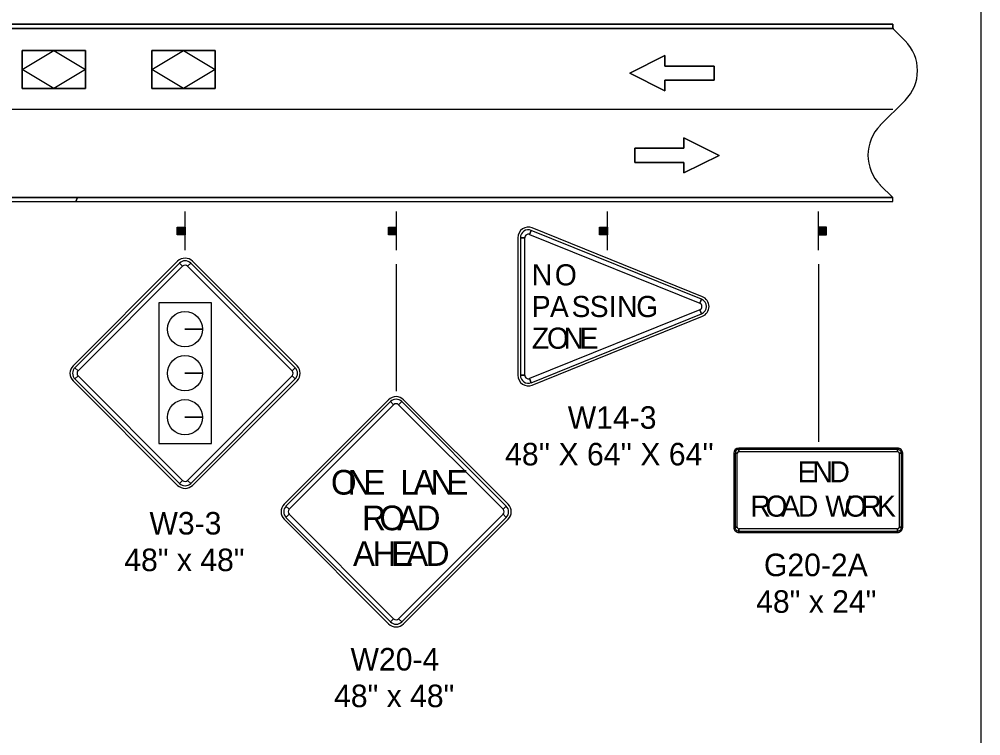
# Model space of a CAD drawing. Extents: x -2134934 to -2127057, y -2139046 to -2137036.
# Drawn here: x -2132482 to -2131799, y -2138047 to -2137539 of the extents above; entities that cross this region are included whole.
import ezdxf

# ---------------------------------------------------------------- set-up
doc = ezdxf.new("R2010")
doc.units = 0
for name, color, linetype in [('Barrier', 7, 'Continuous'), ('BridgeSuperStructureExisting', 7, 'Continuous'), ('Default', 7, 'Continuous'), ('DsnShtPlotIdentification', 7, 'Continuous'), ('dsnTextFinalPlan', 7, 'Continuous')]:
    doc.layers.add(name, color=color, linetype=linetype)

msp = doc.modelspace()

# ---------------------------------------------------------------- linework, layer by layer
at = {"layer": 'Barrier'}
for p, q in [((-2132119.84, -2137691.45), (-2132118.67, -2137688.56)), ((-2131997.15, -2137735.69), (-2132117.97, -2137686.82)), ((-2132128.28, -2137693.77), (-2132128.28, -2137791.52)), ((-2132126.41, -2137693.77), (-2132123.28, -2137693.77)), ((-2132369.87, -2137710.55), (-2132444.11, -2137784.8)), ((-2132368.54, -2137711.88), (-2132366.33, -2137714.08)), ((-2132362.8, -2137714.08), (-2132360.59, -2137711.88)), ((-2132285.02, -2137784.8), (-2132359.26, -2137710.55)), ((-2131997.85, -2137737.43), (-2131999.02, -2137740.33)), ((-2132117.97, -2137798.48), (-2131997.15, -2137749.6)), ((-2131999.02, -2137744.96), (-2131997.85, -2137747.86)), ((-2132352.16, -2137758.77), (-2132364.66, -2137758.77)), ((-2132364.66, -2137758.77), (-2132352.16, -2137758.77)), ((-2132440.58, -2137788.33), (-2132442.79, -2137786.12)), ((-2132442.79, -2137794.08), (-2132440.58, -2137791.87)), ((-2132352.16, -2137790.02), (-2132364.66, -2137790.02)), ((-2132364.66, -2137790.02), (-2132352.16, -2137790.02)), ((-2132286.34, -2137786.12), (-2132288.55, -2137788.33)), ((-2132288.55, -2137791.87), (-2132286.34, -2137794.08)), ((-2132123.28, -2137791.52), (-2132126.41, -2137791.52)), ((-2132444.11, -2137795.4), (-2132369.87, -2137869.65)), ((-2132359.26, -2137869.65), (-2132285.02, -2137795.4)), ((-2132118.67, -2137796.74), (-2132119.84, -2137793.84)), ((-2132219.98, -2137808.84), (-2132294.23, -2137883.09)), ((-2132218.66, -2137810.17), (-2132216.45, -2137812.38)), ((-2132212.91, -2137812.38), (-2132210.7, -2137810.17)), ((-2132135.13, -2137883.09), (-2132209.38, -2137808.84)), ((-2132352.16, -2137821.27), (-2132364.66, -2137821.27)), ((-2132364.66, -2137821.27), (-2132352.16, -2137821.27)), ((-2131974.91, -2137846.89), (-2131974.91, -2137899.39)), ((-2131973.97, -2137846.89), (-2131972.41, -2137846.89)), ((-2131858.66, -2137843.14), (-2131971.16, -2137843.14)), ((-2131971.16, -2137845.64), (-2131971.16, -2137844.08)), ((-2131858.66, -2137844.08), (-2131858.66, -2137845.64)), ((-2131857.41, -2137846.89), (-2131855.85, -2137846.89)), ((-2131854.91, -2137899.39), (-2131854.91, -2137846.89)), ((-2132366.33, -2137866.11), (-2132368.54, -2137868.32)), ((-2132360.59, -2137868.32), (-2132362.8, -2137866.11)), ((-2132290.69, -2137886.62), (-2132292.9, -2137884.41)), ((-2132136.46, -2137884.41), (-2132138.66, -2137886.62)), ((-2132294.23, -2137893.69), (-2132219.98, -2137967.94)), ((-2132292.9, -2137892.37), (-2132290.69, -2137890.16)), ((-2132209.38, -2137967.94), (-2132135.13, -2137893.69)), ((-2132138.66, -2137890.16), (-2132136.46, -2137892.37)), ((-2131972.41, -2137899.39), (-2131973.97, -2137899.39)), ((-2131971.16, -2137902.2), (-2131971.16, -2137900.64)), ((-2131858.66, -2137900.64), (-2131858.66, -2137902.2)), ((-2131855.85, -2137899.39), (-2131857.41, -2137899.39)), ((-2131971.16, -2137903.14), (-2131858.66, -2137903.14)), ((-2132216.45, -2137964.41), (-2132218.66, -2137966.61)), ((-2132210.7, -2137966.61), (-2132212.91, -2137964.41))]:
    msp.add_line(p, q, dxfattribs=at)
for points in [[(-2131997.85, -2137737.43), (-2132118.67, -2137688.56), (-2132119.84, -2137691.45), (-2131999.02, -2137740.33), (-2131997.85, -2137737.43)], [(-2132126.41, -2137693.77), (-2132126.41, -2137791.52), (-2132123.28, -2137791.52), (-2132123.28, -2137693.77), (-2132126.41, -2137693.77)], [(-2132368.54, -2137711.88), (-2132442.79, -2137786.12), (-2132440.58, -2137788.33), (-2132366.33, -2137714.08), (-2132368.54, -2137711.88)], [(-2132286.34, -2137786.12), (-2132360.59, -2137711.88), (-2132362.8, -2137714.08), (-2132288.55, -2137788.33), (-2132286.34, -2137786.12)], [(-2132345.83, -2137740.15), (-2132383.3, -2137740.15), (-2132383.3, -2137840.04), (-2132345.83, -2137840.04), (-2132345.83, -2137740.15)], [(-2132118.67, -2137796.74), (-2131997.85, -2137747.86), (-2131999.02, -2137744.96), (-2132119.84, -2137793.84), (-2132118.67, -2137796.74)], [(-2132442.79, -2137794.08), (-2132368.54, -2137868.32), (-2132366.33, -2137866.11), (-2132440.58, -2137791.87), (-2132442.79, -2137794.08)], [(-2132360.59, -2137868.32), (-2132286.34, -2137794.08), (-2132288.55, -2137791.87), (-2132362.8, -2137866.11), (-2132360.59, -2137868.32)], [(-2132218.66, -2137810.17), (-2132292.9, -2137884.41), (-2132290.69, -2137886.62), (-2132216.45, -2137812.38), (-2132218.66, -2137810.17)], [(-2132136.46, -2137884.41), (-2132210.7, -2137810.17), (-2132212.91, -2137812.38), (-2132138.66, -2137886.62), (-2132136.46, -2137884.41)], [(-2131973.97, -2137846.89), (-2131973.97, -2137899.39), (-2131972.41, -2137899.39), (-2131972.41, -2137846.89), (-2131973.97, -2137846.89)], [(-2131858.66, -2137844.08), (-2131971.16, -2137844.08), (-2131971.16, -2137845.64), (-2131858.66, -2137845.64), (-2131858.66, -2137844.08)], [(-2131855.85, -2137899.39), (-2131855.85, -2137846.89), (-2131857.41, -2137846.89), (-2131857.41, -2137899.39), (-2131855.85, -2137899.39)], [(-2132292.9, -2137892.37), (-2132218.66, -2137966.61), (-2132216.45, -2137964.41), (-2132290.69, -2137890.16), (-2132292.9, -2137892.37)], [(-2132210.7, -2137966.61), (-2132136.46, -2137892.37), (-2132138.66, -2137890.16), (-2132212.91, -2137964.41), (-2132210.7, -2137966.61)], [(-2131971.16, -2137902.2), (-2131858.66, -2137902.2), (-2131858.66, -2137900.64), (-2131971.16, -2137900.64), (-2131971.16, -2137902.2)]]:
    msp.add_lwpolyline(points, close=True, dxfattribs=at)
for centre in [(-2132364.66, -2137758.77), (-2132364.66, -2137790.02), (-2132364.66, -2137821.27)]:
    msp.add_circle(centre, 12.5, dxfattribs=at)
for centre, radius, start, end in [((-2132120.78, -2137693.77), 7.5, 67.97571, 179.99985), ((-2132120.78, -2137693.77), 5.62, 67.97571, 179.99985), ((-2132120.78, -2137693.77), 2.5, 67.97571, 179.99985), ((-2132364.57, -2137715.85), 7.5, 44.99999, 134.99974), ((-2132364.57, -2137715.85), 5.62, 44.99999, 134.99974), ((-2132364.57, -2137715.85), 2.5, 44.99999, 134.99974), ((-2131999.96, -2137742.65), 5.62, 292.02456, 67.97541), ((-2131999.96, -2137742.65), 7.5, 292.02456, 67.97598), ((-2131999.96, -2137742.65), 2.5, 292.02456, 67.97541), ((-2132438.81, -2137790.1), 7.5, 134.99974, 224.99995), ((-2132290.32, -2137790.1), 7.5, 315.00016, 44.9998), ((-2132438.81, -2137790.1), 5.62, 134.99974, 224.99995), ((-2132438.81, -2137790.1), 2.5, 134.99974, 224.99995), ((-2132290.32, -2137790.1), 2.5, 315.00016, 44.9998), ((-2132290.32, -2137790.1), 5.62, 315.00016, 44.9998), ((-2132120.78, -2137791.52), 7.5, 179.99985, 292.02456), ((-2132120.78, -2137791.52), 5.62, 179.99985, 292.02456), ((-2132120.78, -2137791.52), 2.5, 179.99985, 292.02456), ((-2132214.68, -2137814.15), 7.5, 44.99999, 134.99974), ((-2132214.68, -2137814.15), 5.62, 44.99999, 134.99974), ((-2132214.68, -2137814.15), 2.5, 44.99999, 134.99974), ((-2131971.16, -2137846.89), 3.75, 90.00021, 179.99985), ((-2131971.16, -2137846.89), 2.81, 90.00021, 179.99985), ((-2131971.16, -2137846.89), 1.25, 90.00021, 179.99985), ((-2131858.66, -2137846.89), 3.75, 0, 90.00021), ((-2131858.66, -2137846.89), 2.81, 0, 90.00021), ((-2131858.66, -2137846.89), 1.25, 0, 90.00021), ((-2132364.57, -2137864.34), 2.5, 224.99995, 315.00016), ((-2132364.57, -2137864.34), 7.5, 224.99995, 315.00016), ((-2132364.57, -2137864.34), 5.62, 224.99995, 315.00016), ((-2132288.92, -2137888.39), 7.5, 134.99974, 224.99995), ((-2132288.92, -2137888.39), 5.62, 134.99974, 224.99995), ((-2132288.92, -2137888.39), 2.5, 134.99974, 224.99995), ((-2132140.43, -2137888.39), 2.5, 315.00016, 44.9998), ((-2132140.43, -2137888.39), 5.62, 315.00016, 44.9998), ((-2132140.43, -2137888.39), 7.5, 315.00016, 44.9998), ((-2131971.16, -2137899.39), 3.75, 179.99985, 270.00006), ((-2131971.16, -2137899.39), 2.81, 179.99985, 270.00006), ((-2131971.16, -2137899.39), 1.25, 179.99985, 270.00006), ((-2131858.66, -2137899.39), 3.75, 270.00006, 0.00027), ((-2131858.66, -2137899.39), 2.81, 270.00006, 0.00027), ((-2131858.66, -2137899.39), 1.25, 270.00006, 0.00027), ((-2132214.68, -2137962.64), 7.5, 224.99995, 315.00016), ((-2132214.68, -2137962.64), 5.62, 224.99995, 315.00016), ((-2132214.68, -2137962.64), 2.5, 224.99995, 315.00016)]:
    msp.add_arc(centre, radius, start, end, dxfattribs=at)
at = {"layer": 'BridgeSuperStructureExisting'}
for p, q in [((-2131861.99, -2137545.16), (-2133174.44, -2137545.16)), ((-2131853.21, -2137553.94), (-2131861.99, -2137545.16)), ((-2131853.2, -2137553.95), (-2131861.99, -2137545.16)), ((-2132480.28, -2137587.78), (-2132480.28, -2137560.78)), ((-2132480.28, -2137560.78), (-2132435.28, -2137560.78)), ((-2132480.28, -2137587.78), (-2132480.28, -2137560.78)), ((-2132480.28, -2137560.78), (-2132435.28, -2137560.78)), ((-2132435.28, -2137560.78), (-2132480.28, -2137560.78)), ((-2132480.28, -2137560.78), (-2132480.28, -2137587.78)), ((-2132435.28, -2137587.78), (-2132435.28, -2137560.78)), ((-2132435.28, -2137560.78), (-2132435.28, -2137587.78)), ((-2132435.28, -2137587.78), (-2132435.28, -2137560.78)), ((-2132388.09, -2137587.86), (-2132388.09, -2137560.86)), ((-2132388.09, -2137560.86), (-2132343.09, -2137560.86)), ((-2132388.09, -2137587.86), (-2132388.09, -2137560.86)), ((-2132388.09, -2137560.86), (-2132343.09, -2137560.86)), ((-2132343.09, -2137560.86), (-2132388.09, -2137560.86)), ((-2132388.09, -2137560.86), (-2132388.09, -2137587.86)), ((-2132343.09, -2137587.86), (-2132343.09, -2137560.86)), ((-2132343.09, -2137560.86), (-2132343.09, -2137587.86)), ((-2132343.09, -2137587.86), (-2132343.09, -2137560.86)), ((-2132480.28, -2137587.78), (-2132435.28, -2137587.78)), ((-2132435.28, -2137587.78), (-2132480.28, -2137587.78)), ((-2132480.28, -2137587.78), (-2132435.28, -2137587.78)), ((-2132388.09, -2137587.86), (-2132343.09, -2137587.86)), ((-2132343.09, -2137587.86), (-2132388.09, -2137587.86)), ((-2132388.09, -2137587.86), (-2132343.09, -2137587.86)), ((-2131870.78, -2137613.94), (-2131853.21, -2137596.37)), ((-2131870.78, -2137613.95), (-2131853.2, -2137596.37)), ((-2131861.99, -2137665.16), (-2131870.78, -2137656.37)), ((-2131861.99, -2137665.16), (-2131870.78, -2137656.37)), ((-2133364.44, -2137665.16), (-2131861.99, -2137665.16)), ((-2132364.45, -2137702.66), (-2132364.45, -2137675.16)), ((-2132214.45, -2137702.66), (-2132214.45, -2137675.16)), ((-2132064.45, -2137702.66), (-2132064.45, -2137675.16)), ((-2131914.64, -2137702.66), (-2131914.64, -2137675.16)), ((-2132369.77, -2137691.8), (-2132369.77, -2137686.21)), ((-2132369.45, -2137686.21), (-2132369.45, -2137691.8)), ((-2132369.23, -2137691.8), (-2132369.23, -2137686.21)), ((-2132368.91, -2137686.21), (-2132368.91, -2137691.8)), ((-2132368.68, -2137691.8), (-2132368.7, -2137686.21)), ((-2132368.27, -2137686.21), (-2132368.25, -2137691.8)), ((-2132368.05, -2137691.8), (-2132368.05, -2137686.21)), ((-2132367.62, -2137686.21), (-2132367.62, -2137691.8)), ((-2132367.24, -2137691.8), (-2132367.24, -2137686.21)), ((-2132366.92, -2137686.21), (-2132366.9, -2137691.8)), ((-2132366.7, -2137691.8), (-2132366.7, -2137686.21)), ((-2132366.43, -2137686.21), (-2132366.43, -2137691.8)), ((-2132366.1, -2137691.8), (-2132366.1, -2137686.21)), ((-2132365.89, -2137686.21), (-2132365.89, -2137691.8)), ((-2132365.67, -2137691.8), (-2132365.67, -2137686.21)), ((-2132365.4, -2137686.21), (-2132365.4, -2137691.8)), ((-2132365.14, -2137691.8), (-2132365.14, -2137686.21)), ((-2132364.86, -2137686.21), (-2132364.86, -2137691.8)), ((-2132219.77, -2137691.8), (-2132219.77, -2137686.21)), ((-2132219.45, -2137686.21), (-2132219.45, -2137691.8)), ((-2132219.23, -2137691.8), (-2132219.23, -2137686.21)), ((-2132218.91, -2137686.21), (-2132218.91, -2137691.8)), ((-2132218.69, -2137691.8), (-2132218.7, -2137686.21)), ((-2132218.27, -2137686.21), (-2132218.25, -2137691.8)), ((-2132218.05, -2137691.8), (-2132218.05, -2137686.21)), ((-2132217.62, -2137686.21), (-2132217.62, -2137691.8)), ((-2132217.24, -2137691.8), (-2132217.24, -2137686.21)), ((-2132216.92, -2137686.21), (-2132216.9, -2137691.8)), ((-2132216.7, -2137691.8), (-2132216.7, -2137686.21)), ((-2132216.43, -2137686.21), (-2132216.43, -2137691.8)), ((-2132216.1, -2137691.8), (-2132216.1, -2137686.21)), ((-2132215.89, -2137686.21), (-2132215.89, -2137691.8)), ((-2132215.67, -2137691.8), (-2132215.67, -2137686.21)), ((-2132215.4, -2137686.21), (-2132215.4, -2137691.8)), ((-2132215.14, -2137691.8), (-2132215.14, -2137686.21)), ((-2132214.86, -2137686.21), (-2132214.86, -2137691.8)), ((-2132069.77, -2137691.8), (-2132069.77, -2137686.21)), ((-2132069.45, -2137686.21), (-2132069.45, -2137691.8)), ((-2132069.23, -2137691.8), (-2132069.23, -2137686.21)), ((-2132068.91, -2137686.21), (-2132068.91, -2137691.8)), ((-2132068.69, -2137691.8), (-2132068.7, -2137686.21)), ((-2132068.27, -2137686.21), (-2132068.25, -2137691.8)), ((-2132068.05, -2137691.8), (-2132068.05, -2137686.21)), ((-2132067.62, -2137686.21), (-2132067.62, -2137691.8)), ((-2132067.24, -2137691.8), (-2132067.24, -2137686.21)), ((-2132066.92, -2137686.21), (-2132066.9, -2137691.8)), ((-2132066.7, -2137691.8), (-2132066.7, -2137686.21)), ((-2132066.43, -2137686.21), (-2132066.43, -2137691.8)), ((-2132066.1, -2137691.8), (-2132066.1, -2137686.21)), ((-2132065.89, -2137686.21), (-2132065.89, -2137691.8)), ((-2132065.67, -2137691.8), (-2132065.67, -2137686.21)), ((-2132065.4, -2137686.21), (-2132065.4, -2137691.8)), ((-2132065.14, -2137691.8), (-2132065.14, -2137686.21)), ((-2132064.86, -2137686.21), (-2132064.86, -2137691.8)), ((-2131914.22, -2137686.21), (-2131914.22, -2137691.8)), ((-2131913.94, -2137691.8), (-2131913.94, -2137686.21)), ((-2131913.68, -2137686.21), (-2131913.68, -2137691.8)), ((-2131913.42, -2137691.8), (-2131913.42, -2137686.21)), ((-2131913.19, -2137686.21), (-2131913.19, -2137691.8)), ((-2131912.99, -2137691.8), (-2131912.99, -2137686.21)), ((-2131912.65, -2137686.21), (-2131912.65, -2137691.8)), ((-2131912.39, -2137691.8), (-2131912.39, -2137686.21)), ((-2131912.16, -2137686.21), (-2131912.18, -2137691.8)), ((-2131911.84, -2137691.8), (-2131911.84, -2137686.21)), ((-2131911.47, -2137686.21), (-2131911.47, -2137691.8)), ((-2131911.04, -2137691.8), (-2131911.04, -2137686.21)), ((-2131910.81, -2137686.21), (-2131910.83, -2137691.8)), ((-2131910.4, -2137691.8), (-2131910.38, -2137686.21)), ((-2131910.17, -2137686.21), (-2131910.17, -2137691.8)), ((-2131909.85, -2137691.8), (-2131909.85, -2137686.21)), ((-2131909.63, -2137686.21), (-2131909.63, -2137691.8)), ((-2131909.31, -2137691.8), (-2131909.31, -2137686.21)), ((-2132214.45, -2137802.66), (-2132214.45, -2137712.66)), ((-2131914.45, -2137838.71), (-2131914.45, -2137712.66))]:
    msp.add_line(p, q, dxfattribs=at)
for points in [[(-2131988.74, -2137582), (-2131988.74, -2137572), (-2132023.74, -2137572), (-2132023.74, -2137564.5), (-2132048.74, -2137577), (-2132023.74, -2137589.5), (-2132023.74, -2137582)], [(-2132045.26, -2137630.33), (-2132045.26, -2137640.33), (-2132010.26, -2137640.33), (-2132010.26, -2137647.83), (-2131985.26, -2137635.33), (-2132010.26, -2137622.83), (-2132010.26, -2137630.33)], [(-2132364.54, -2137686.21), (-2132364.54, -2137691.84), (-2132370.17, -2137691.84), (-2132370.17, -2137686.21)], [(-2132214.54, -2137686.21), (-2132214.54, -2137691.84), (-2132220.17, -2137691.84), (-2132220.17, -2137686.21)], [(-2132064.54, -2137686.21), (-2132064.54, -2137691.84), (-2132070.17, -2137691.84), (-2132070.17, -2137686.21)], [(-2131914.54, -2137686.21), (-2131914.54, -2137691.84), (-2131908.92, -2137691.84), (-2131908.92, -2137686.21)]]:
    msp.add_lwpolyline(points, close=True, dxfattribs=at)
for points in [[(-2132023.74, -2137582), (-2132023.74, -2137589.5), (-2132048.74, -2137577), (-2132023.74, -2137564.5), (-2132023.74, -2137572), (-2131988.74, -2137572), (-2131988.74, -2137582), (-2132023.74, -2137582)], [(-2132010.26, -2137630.33), (-2132010.26, -2137622.83), (-2131985.26, -2137635.33), (-2132010.26, -2137647.83), (-2132010.26, -2137640.33), (-2132045.26, -2137640.33), (-2132045.26, -2137630.33), (-2132010.26, -2137630.33)]]:
    msp.add_lwpolyline(points, dxfattribs=at)
for centre, start, end in [((-2131874.42, -2137575.16), 315, 45), ((-2131874.42, -2137575.16), 315, 45), ((-2131849.56, -2137635.16), 135, 225), ((-2131849.56, -2137635.16), 135, 225)]:
    msp.add_arc(centre, 30, start, end, dxfattribs=at)
at = {"layer": 'Default'}
msp.add_lwpolyline([(-2134934.44, -2137035.95), (-2131799.45, -2137035.95), (-2131799.45, -2139045.94), (-2134934.44, -2139045.94)], close=True, dxfattribs=at)
at = {"layer": 'DsnShtPlotIdentification'}
for p, q in [((-2131861.99, -2137542.16), (-2132547.01, -2137542.16)), ((-2132509.45, -2137545.16), (-2131861.99, -2137545.16)), ((-2131861.99, -2137542.16), (-2131861.99, -2137545.16)), ((-2131861.99, -2137545.16), (-2131861.99, -2137542.16)), ((-2131861.95, -2137602.66), (-2132514.45, -2137602.66)), ((-2133364.44, -2137665.16), (-2131861.99, -2137665.16)), ((-2133364.44, -2137665.16), (-2131861.99, -2137665.16)), ((-2133364.44, -2137668.16), (-2131861.99, -2137668.16)), ((-2132441.05, -2137665.16), (-2132714.94, -2137665.16)), ((-2132714.94, -2137668.16), (-2132442.06, -2137668.16)), ((-2132442.06, -2137668.16), (-2132441.05, -2137665.16)), ((-2132441.05, -2137665.16), (-2132442.06, -2137668.16)), ((-2132442.06, -2137668.16), (-2131861.99, -2137668.16)), ((-2131861.99, -2137665.16), (-2132441.05, -2137665.16)), ((-2131861.99, -2137668.16), (-2131861.99, -2137665.16)), ((-2131861.99, -2137668.16), (-2131861.99, -2137665.16))]:
    msp.add_line(p, q, dxfattribs=at)
for points in [[(-2133174.44, -2137542.16), (-2131861.99, -2137542.16)], [(-2133174.44, -2137545.16), (-2131861.99, -2137545.16)], [(-2133173.75, -2137545.16), (-2131861.29, -2137545.16)]]:
    msp.add_lwpolyline(points, dxfattribs=at)
at = {"layer": 'dsnTextFinalPlan'}
for points in [[(-2132480.28, -2137574.28), (-2132457.78, -2137560.78), (-2132435.28, -2137574.28), (-2132457.78, -2137587.78)], [(-2132388.09, -2137574.36), (-2132365.59, -2137560.86), (-2132343.09, -2137574.36), (-2132365.59, -2137587.86)]]:
    msp.add_lwpolyline(points, close=True, dxfattribs=at)

# ---------------------------------------------------------------- texts
at = {"layer": 'Barrier'}
for s, height, p in [('N', 15, (-2132118.31, -2137727.65)), ('O', 15, (-2132101.97, -2137727.65)), ('P', 15, (-2132118.31, -2137750.15)), ('A', 15, (-2132105.42, -2137750.15)), ('S', 15, (-2132090.07, -2137750.15)), ('S', 15, (-2132077.18, -2137750.15)), ('I', 15, (-2132063.59, -2137750.15)), ('N', 15, (-2132057.73, -2137750.15)), ('G', 15, (-2132044.13, -2137750.15)), ('Z', 15, (-2132118.31, -2137772.65)), ('O', 15, (-2132107.58, -2137772.65)), ('N', 15, (-2132095.75, -2137772.65)), ('E', 15, (-2132084.38, -2137772.65)), ('W14-3', 16, (-2132092.77, -2137829.48)), ("48'' X 64'' X 64''", 16, (-2132137.26, -2137855.47)), ('E', 15, (-2131929.58, -2137867.51)), ('N', 15, (-2131918.96, -2137867.51)), ('D', 15, (-2131906.88, -2137867.51)), ('O', 17.5, (-2132260.96, -2137876.2)), ('N', 17.5, (-2132249.19, -2137876.2)), ('E', 17.5, (-2132237.96, -2137876.2)), ('L', 17.5, (-2132211.71, -2137876.2)), ('A', 17.5, (-2132202.51, -2137876.2)), ('N', 17.5, (-2132190.25, -2137876.2)), ('E', 17.5, (-2132179.02, -2137876.2)), ('R', 15, (-2131963.05, -2137891.89)), ('O', 15, (-2131952.36, -2137891.89)), ('A', 15, (-2131941.21, -2137891.89)), ('D', 15, (-2131929.35, -2137891.89)), ('W', 15, (-2131909.9, -2137891.89)), ('O', 15, (-2131896.16, -2137891.89)), ('R', 15, (-2131884.4, -2137891.89)), ('K', 15, (-2131873.1, -2137891.89)), ('R', 17.5, (-2132238.86, -2137901.52)), ('O', 17.5, (-2132226.57, -2137901.52)), ('A', 17.5, (-2132213.73, -2137901.52)), ('D', 17.5, (-2132200.07, -2137901.52)), ('W3-3', 16, (-2132389.86, -2137904.56)), ('48" x 48"', 16, (-2132407.73, -2137930.56)), ('A', 17.5, (-2132245.29, -2137926.83)), ('H', 17.5, (-2132231.43, -2137926.83)), ('E', 17.5, (-2132218.21, -2137926.83)), ('A', 17.5, (-2132207.5, -2137926.83)), ('D', 17.5, (-2132193.63, -2137926.83)), ('G20-2A', 16, (-2131953.44, -2137934.14)), ('48" x 24"', 16, (-2131958.97, -2137960.14)), ('W20-4', 16, (-2132247.05, -2138001.14)), ('48" x 48"', 16, (-2132258.75, -2138027.14))]:
    msp.add_text(s, height=height, dxfattribs=at).set_placement(p)

doc.saveas('drawing.dxf')
